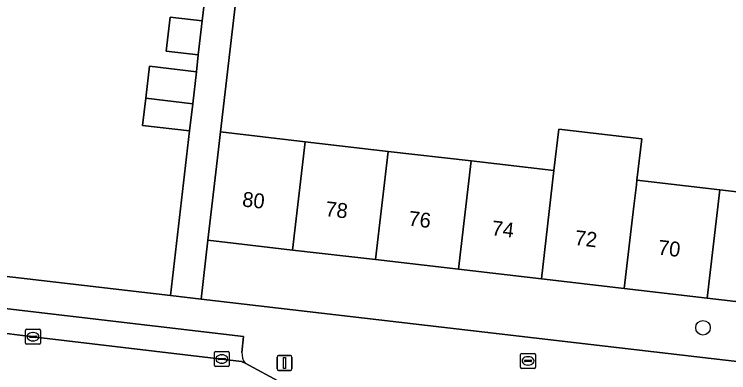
# Model space of a CAD drawing. Extents: x 162250 to 162661, y 380743 to 381606.
# Drawn here: x 162291.22 to 162339.15, y 380906.87 to 380930.93 of the extents above; entities that cross this region are included whole.
import ezdxf

# ---------------------------------------------------------------- set-up
doc = ezdxf.new("R2010")
doc.units = 0
for name, color, linetype in [('IMGEO_Boom', 7, 'Continuous'), ('IMGEO_Brandkraan', 7, 'Continuous'), ('IMGEO_Erf', 7, 'Continuous'), ('IMGEO_Kolk', 7, 'Continuous'), ('IMGEO_Lichtmast', 7, 'Continuous'), ('IMGEO_Pand', 7, 'Continuous'), ('IMGEO_Pand_nummerreeks', 7, 'Continuous'), ('IMGEO_Parkeervlak_open', 7, 'Continuous'), ('IMGEO_Rijbaan_lokaal_open', 7, 'Continuous'), ('IMGEO_Voetpad_open', 7, 'Continuous')]:
    doc.layers.add(name, color=color, linetype=linetype)

msp = doc.modelspace()

# ---------------------------------------------------------------- linework, layer by layer
at = {"layer": 'IMGEO_Boom'}
msp.add_circle((162337.422, 380909.889), 0.489, dxfattribs=at)
at = {"layer": 'IMGEO_Brandkraan'}
for p, q in [((162325.185, 380907.24), (162325.185, 380908.092)), ((162325.26, 380908.166), (162326.112, 380908.166)), ((162325.673, 380907.946), (162325.698, 380907.946)), ((162326.186, 380908.092), (162326.186, 380907.24)), ((162325.444, 380907.66), (162325.444, 380907.672)), ((162325.882, 380907.623), (162325.484, 380907.623)), ((162325.487, 380907.709), (162325.885, 380907.709)), ((162325.696, 380907.386), (162325.671, 380907.386)), ((162325.928, 380907.672), (162325.928, 380907.66)), ((162326.112, 380907.166), (162325.26, 380907.166))]:
    msp.add_line(p, q, dxfattribs=at)
for points in [[(162325.185, 380907.24), (162325.185, 380908.092)], [(162325.26, 380908.166), (162326.112, 380908.166)], [(162326.186, 380908.092), (162326.186, 380907.24)], [(162326.112, 380907.166), (162325.26, 380907.166)]]:
    msp.add_lwpolyline(points, dxfattribs=at)
for centre, radius, start, end in [((162325.262, 380908.09), 0.0765, 91.552, 178.448), ((162325.262, 380908.09), 0.0765, 91.552, 178.448), ((162326.11, 380908.09), 0.0765, 1.552, 88.448), ((162326.11, 380908.09), 0.0765, 1.552, 88.448), ((162325.484, 380907.669), 0.0403, 85.8775, 175.7526), ((162325.481, 380907.659), 0.0366, 178.938, 274.7102), ((162325.885, 380907.666), 0.043, 264.8664, 352.4533), ((162325.889, 380907.671), 0.0386, 1.7309, 96.639), ((162325.262, 380907.242), 0.0765, 181.552, 268.448), ((162325.262, 380907.242), 0.0765, 181.552, 268.448), ((162326.11, 380907.242), 0.0765, 271.552, 358.448), ((162326.11, 380907.242), 0.0765, 271.552, 358.448)]:
    msp.add_arc(centre, radius, start, end, dxfattribs=at)
for centre, major_axis, ratio, start_param, end_param in [((162325.672, 380907.666), (-0.387, 0.002), 0.722429, 4.712389, 7.853982), ((162325.697, 380907.666), (-0.39, 0.002), 0.717154, 1.570796, 4.712389)]:
    msp.add_ellipse(centre, major_axis=major_axis, ratio=ratio, start_param=start_param, end_param=end_param, dxfattribs=at)
at = {"layer": 'IMGEO_Erf'}
for points in [[(162280.452, 380944.613), (162277.054, 380914.909), (162301.694, 380912.045), (162302.979, 380923.101), (162299.829, 380923.469), (162300.041, 380925.289), (162300.292, 380927.436), (162303.443, 380927.069), (162303.558, 380928.199), (162301.415, 380928.447), (162301.681, 380930.745), (162303.824, 380930.497), (162304.272, 380934.244)], [(162307.019, 380939.931), (162305.058, 380923.033), (162310.74, 380922.374), (162316.303, 380921.73), (162321.864, 380921.085), (162327.427, 380920.44), (162327.749, 380923.209), (162333.311, 380922.565), (162332.989, 380919.795), (162338.551, 380919.15), (162344.113, 380918.505)]]:
    msp.add_lwpolyline(points, dxfattribs=at)
msp.add_lwpolyline([(162359.955, 380909.304), (162354.393, 380909.948), (162348.831, 380910.593), (162343.269, 380911.238), (162337.707, 380911.883), (162332.144, 380912.528), (162326.582, 380913.172), (162321.02, 380913.817), (162315.458, 380914.462), (162309.896, 380915.106), (162304.215, 380915.765), (162303.756, 380911.805), (162387.38, 380902.085), (162387.886, 380906.066), (162382.204, 380906.725), (162376.642, 380907.369), (162371.079, 380908.014), (162365.517, 380908.659)], close=True, dxfattribs=at)
at = {"layer": 'IMGEO_Kolk'}
for p, q in [((162291.975, 380908.865), (162291.975, 380909.717)), ((162292.05, 380909.791), (162292.902, 380909.791)), ((162292.976, 380909.717), (162292.976, 380908.865)), ((162292.234, 380909.285), (162292.234, 380909.297)), ((162292.672, 380909.248), (162292.274, 380909.248)), ((162292.277, 380909.334), (162292.675, 380909.334)), ((162292.463, 380909.571), (162292.488, 380909.571)), ((162292.718, 380909.297), (162292.718, 380909.285)), ((162292.902, 380908.791), (162292.05, 380908.791)), ((162292.486, 380909.011), (162292.461, 380909.011)), ((162304.641, 380907.369), (162304.641, 380908.221)), ((162304.716, 380908.295), (162305.568, 380908.295)), ((162305.642, 380908.221), (162305.642, 380907.369)), ((162304.9, 380907.789), (162304.9, 380907.801)), ((162305.338, 380907.752), (162304.94, 380907.752)), ((162304.943, 380907.838), (162305.341, 380907.838)), ((162305.129, 380908.075), (162305.154, 380908.075)), ((162305.384, 380907.801), (162305.384, 380907.789)), ((162305.568, 380907.295), (162304.716, 380907.295)), ((162305.152, 380907.515), (162305.127, 380907.515))]:
    msp.add_line(p, q, dxfattribs=at)
for points in [[(162291.975, 380908.865), (162291.975, 380909.717)], [(162292.05, 380909.791), (162292.902, 380909.791)], [(162292.976, 380909.717), (162292.976, 380908.865)], [(162292.902, 380908.791), (162292.05, 380908.791)], [(162304.641, 380907.369), (162304.641, 380908.221)], [(162304.716, 380908.295), (162305.568, 380908.295)], [(162305.642, 380908.221), (162305.642, 380907.369)], [(162305.568, 380907.295), (162304.716, 380907.295)]]:
    msp.add_lwpolyline(points, dxfattribs=at)
for centre, radius, start, end in [((162292.052, 380909.715), 0.0765, 91.552, 178.448), ((162292.052, 380909.715), 0.0765, 91.552, 178.448), ((162292.9, 380909.715), 0.0765, 1.552, 88.448), ((162292.9, 380909.715), 0.0765, 1.552, 88.448), ((162292.274, 380909.294), 0.0403, 85.8775, 175.7526), ((162292.271, 380909.284), 0.0366, 178.938, 274.7102), ((162292.675, 380909.291), 0.043, 264.8664, 352.4533), ((162292.679, 380909.296), 0.0386, 1.7309, 96.639), ((162292.052, 380908.867), 0.0765, 181.552, 268.448), ((162292.052, 380908.867), 0.0765, 181.552, 268.448), ((162292.9, 380908.867), 0.0765, 271.552, 358.448), ((162292.9, 380908.867), 0.0765, 271.552, 358.448), ((162304.718, 380908.219), 0.0765, 91.552, 178.448), ((162304.718, 380908.219), 0.0765, 91.552, 178.448), ((162305.566, 380908.219), 0.0765, 1.552, 88.448), ((162305.566, 380908.219), 0.0765, 1.552, 88.448), ((162304.94, 380907.798), 0.0403, 85.8775, 175.7526), ((162304.937, 380907.788), 0.0366, 178.938, 274.7102), ((162305.341, 380907.795), 0.043, 264.8664, 352.4533), ((162305.345, 380907.8), 0.0386, 1.7309, 96.639), ((162304.718, 380907.371), 0.0765, 181.552, 268.448), ((162304.718, 380907.371), 0.0765, 181.552, 268.448), ((162305.566, 380907.371), 0.0765, 271.552, 358.448), ((162305.566, 380907.371), 0.0765, 271.552, 358.448)]:
    msp.add_arc(centre, radius, start, end, dxfattribs=at)
for centre, major_axis, ratio, start_param, end_param in [((162292.462, 380909.291), (-0.387, 0.002), 0.722429, 4.712389, 7.853982), ((162292.487, 380909.291), (-0.39, 0.002), 0.717154, 1.570796, 4.712389), ((162305.128, 380907.795), (-0.387, 0.002), 0.722429, 4.712389, 7.853982), ((162305.153, 380907.795), (-0.39, 0.002), 0.717154, 1.570796, 4.712389)]:
    msp.add_ellipse(centre, major_axis=major_axis, ratio=ratio, start_param=start_param, end_param=end_param, dxfattribs=at)
at = {"layer": 'IMGEO_Lichtmast'}
for p, q in [((162308.853, 380907.127), (162308.853, 380907.927)), ((162308.853, 380907.927), (162308.853, 380907.127)), ((162308.953, 380908.027), (162309.743, 380908.027)), ((162309.743, 380908.027), (162308.953, 380908.027)), ((162309.843, 380907.927), (162309.843, 380907.127)), ((162309.843, 380907.127), (162309.843, 380907.927)), ((162309.743, 380907.027), (162308.953, 380907.027)), ((162308.953, 380907.027), (162309.743, 380907.027))]:
    msp.add_line(p, q, dxfattribs=at)
msp.add_lwpolyline([(162309.273, 380907.902), (162309.423, 380907.902), (162309.423, 380907.152), (162309.273, 380907.152), (162309.273, 380907.902)], dxfattribs=at)
for centre, start, end in [((162308.953, 380907.927), 90, 180), ((162308.953, 380907.927), 90, 180), ((162309.743, 380907.927), 0, 90), ((162309.743, 380907.927), 360, 90), ((162308.953, 380907.127), 180, 270), ((162308.953, 380907.127), 180, 270), ((162309.743, 380907.127), 270, 0), ((162309.743, 380907.127), 270, 0)]:
    msp.add_arc(centre, 0.1, start, end, dxfattribs=at)
at = {"layer": 'IMGEO_Pand'}
for points in [[(162303.824, 380930.497), (162301.681, 380930.745), (162301.415, 380928.447), (162303.558, 380928.199)], [(162303.192, 380924.925), (162303.443, 380927.069), (162300.292, 380927.436), (162300.041, 380925.289)], [(162303.192, 380924.925), (162300.041, 380925.289), (162299.829, 380923.469), (162302.979, 380923.101)], [(162332.989, 380919.795), (162333.311, 380922.565), (162327.749, 380923.209), (162327.427, 380920.44), (162326.582, 380913.172), (162332.144, 380912.528), (162332.787, 380918.057), (162332.953, 380919.487)], [(162310.74, 380922.374), (162305.058, 380923.033), (162304.744, 380920.327), (162304.215, 380915.765), (162309.896, 380915.106)], [(162310.74, 380922.374), (162309.896, 380915.106), (162315.458, 380914.462), (162316.303, 380921.73)], [(162321.864, 380921.085), (162316.303, 380921.73), (162315.458, 380914.462), (162321.02, 380913.817)], [(162327.427, 380920.44), (162321.864, 380921.085), (162321.02, 380913.817), (162326.582, 380913.172)], [(162338.551, 380919.15), (162332.989, 380919.795), (162332.953, 380919.487), (162332.787, 380918.057), (162332.144, 380912.528), (162337.707, 380911.883)], [(162343.269, 380911.238), (162344.113, 380918.505), (162338.551, 380919.15), (162337.707, 380911.883)]]:
    msp.add_lwpolyline(points, close=True, dxfattribs=at)
at = {"layer": 'IMGEO_Parkeervlak_open'}
msp.add_lwpolyline([(162306.485, 380908.235), (162306.605, 380909.301), (162283.346, 380912.031), (162283.121, 380910.597), (162283.046, 380910.457), (162292.66, 380909.267), (162306.458, 380907.638), (162306.705, 380907.505)], dxfattribs=at)
msp.add_arc((162307.756, 380908.22), 1.271, 179.3156, 214.2268, dxfattribs=at)
at = {"layer": 'IMGEO_Rijbaan_lokaal_open'}
msp.add_lwpolyline([(162338.006, 380901.74), (162323.827, 380903.117), (162313.006, 380904.183), (162310.012, 380905.728), (162306.705, 380907.505), (162306.458, 380907.638), (162292.66, 380909.267), (162283.046, 380910.457), (162280.022, 380910.745), (162279.515, 380906.391), (162284.013, 380905.94), (162289.869, 380905.312), (162300.415, 380904.048), (162304.299, 380903.584), (162305.327, 380903.261), (162309.716, 380900.169), (162312.494, 380899.87), (162316.431, 380899.429)], dxfattribs=at)
at = {"layer": 'IMGEO_Voetpad_open'}
for points in [[(162304.272, 380934.244), (162303.824, 380930.497), (162303.558, 380928.199), (162303.443, 380927.069), (162303.192, 380924.925), (162302.979, 380923.101), (162301.694, 380912.045), (162303.756, 380911.805), (162304.215, 380915.765), (162304.744, 380920.327), (162305.058, 380923.033), (162307.019, 380939.931)], [(162446.741, 380900.601), (162441.119, 380900.4), (162435.376, 380900.195), (162435.233, 380904.199), (162432.846, 380904.146), (162430.939, 380904.454), (162424.628, 380905.15), (162418.77, 380905.796), (162412.864, 380906.447), (162406.649, 380907.132), (162403.615, 380907.534), (162403.427, 380905.895), (162390.97, 380907.322), (162391.079, 380908.948), (162388.264, 380909.325), (162387.886, 380906.066), (162387.38, 380902.085), (162303.756, 380911.805), (162301.694, 380912.045), (162277.054, 380914.909), (162276.814, 380911.134)], [(162277.124, 380911.094), (162280.022, 380910.745), (162283.046, 380910.457), (162283.121, 380910.597), (162283.346, 380912.031), (162306.605, 380909.301), (162306.485, 380908.235)], [(162306.705, 380907.505), (162310.012, 380905.728), (162313.006, 380904.183), (162313.223, 380905.978), (162338.073, 380903.225), (162337.968, 380902.03)]]:
    msp.add_lwpolyline(points, dxfattribs=at)
msp.add_arc((162307.756, 380908.22), 1.271, 179.3156, 214.2268, dxfattribs=at)

# ---------------------------------------------------------------- texts
at = {"layer": 'IMGEO_Pand_nummerreeks'}
for s, rotation, p in [('80', 353.3879, (162306.476, 380918.039)), ('78', 353.3879, (162312.054, 380917.393)), ('76', 353.3879, (162317.629, 380916.747)), ('74', 353.3879, (162323.207, 380916.101)), ('72', 353.3881, (162328.782, 380915.454)), ('70', 353.3881, (162334.366, 380914.806))]:
    msp.add_text(s, height=1, rotation=rotation, dxfattribs=at).set_placement(p)

doc.saveas('drawing.dxf')
